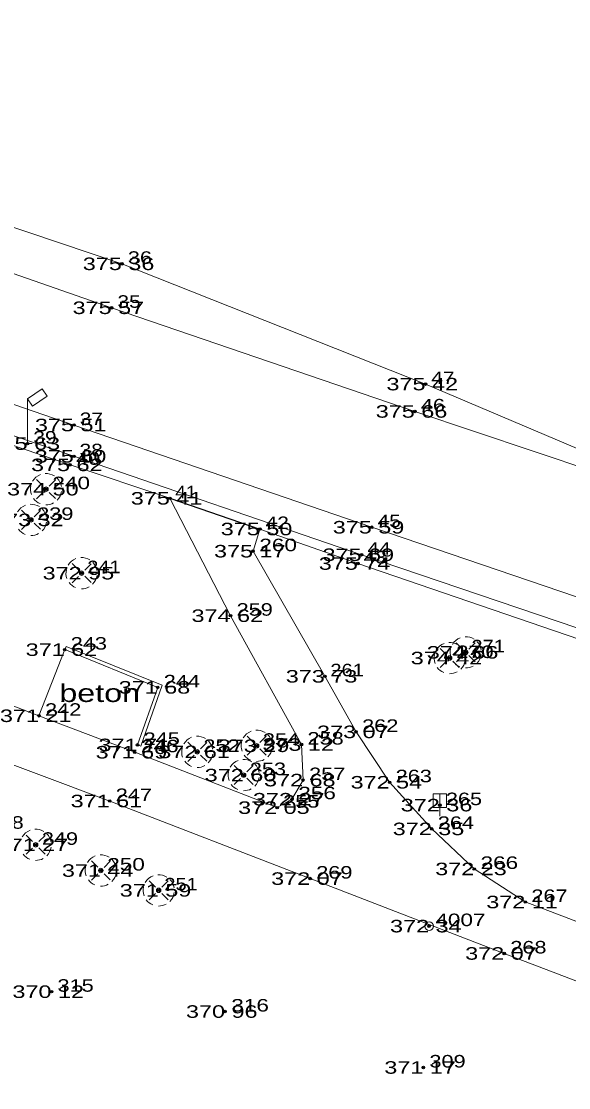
# Model space of a CAD drawing. Extents: x -789669 to -789458, y -977587 to -977420.
# Drawn here: x -789529.3 to -789498.6, y -977510.5 to -977450.8 of the extents above; entities that cross this region are included whole.
import ezdxf
from ezdxf.enums import TextEntityAlignment as Align

# ---------------------------------------------------------------- set-up
doc = ezdxf.new("R2010")
doc.units = 0
doc.header["$LTSCALE"] = 0.28
doc.header["$PDMODE"] = 32
doc.header["$PDSIZE"] = 0.14
for name, color, linetype, lineweight in [('1', 7, 'Continuous', 13), ('2', 7, 'Continuous', 13), ('25', 7, 'Continuous', 13), ('3', 7, 'Continuous', 13), ('33', 7, 'Continuous', 13), ('4', 7, 'Continuous', 13), ('50', 7, 'Continuous', 13)]:
    doc.layers.add(name, color=color, linetype=linetype, lineweight=lineweight)
for name, color, linetype in [('5', 7, 'Continuous'), ('57', 7, 'Continuous'), ('58', 7, 'Continuous'), ('59', 7, 'Continuous')]:
    doc.layers.add(name, color=color, linetype=linetype)

msp = doc.modelspace()

# ---------------------------------------------------------------- linework, layer by layer
at = {"layer": '1'}
msp.add_line((-789488.92, -977486.15), (-789509.64, -977479.12), dxfattribs=at)
for points in [[(-789652.33, -977422.61), (-789627.98, -977430.97), (-789609.02, -977437.54), (-789583.63, -977446.35), (-789563.97, -977453.25), (-789542.04, -977460.63), (-789524.21, -977466.84), (-789507.23, -977472.64), (-789487.17, -977479.36)], [(-789509.64, -977479.12), (-789526.32, -977473.4), (-789544.78, -977467.07), (-789566.2, -977459.68), (-789586.28, -977452.77), (-789604.78, -977446.41), (-789630.61, -977437.53), (-789654.9, -977429.37)], [(-789604.26, -977448.38), (-789586.79, -977454.41), (-789566.59, -977461.37), (-789545.35, -977468.71), (-789526.33, -977475.15), (-789510.21, -977480.66), (-789489.34, -977487.73), (-789463.94, -977496.44)], [(-789528.28, -977489.67), (-789537.88, -977485.96), (-789544.73, -977483.69), (-789553.55, -977480.4), (-789562.72, -977477.06), (-789579.25, -977471.12)], [(-789520.95, -977477.5), (-789517.55, -977484.07), (-789513.58, -977491.28), (-789513.49, -977493.27), (-789514.11, -977494.34), (-789514.94, -977494.81), (-789522.92, -977491.71)], [(-789467.42, -977508.6), (-789477.29, -977504.99), (-789481.22, -977505.18), (-789485.02, -977506.14), (-789492.68, -977503.27), (-789501.04, -977500.09), (-789503.9, -977498.24), (-789506.28, -977496), (-789508.64, -977493.39), (-789510.52, -977490.57), (-789512.27, -977487.46), (-789516.29, -977480.46), (-789515.91, -977479.22)], [(-789522.92, -977491.71), (-789528.28, -977489.67), (-789526.84, -977485.97)], [(-789542.34, -977487.22), (-789536.41, -977489.92), (-789524.32, -977494.44)], [(-789482.95, -977510.48), (-789493.26, -977506.39), (-789502.22, -977502.97), (-789513.09, -977498.78), (-789524.32, -977494.44)]]:
    msp.add_lwpolyline(points, dxfattribs=at)
at = {"layer": '2'}
msp.add_lwpolyline([(-789651.99, -977420.32), (-789627.42, -977429.7), (-789608.58, -977435.72), (-789582.71, -977444.73), (-789563.37, -977451.38), (-789541.29, -977458.45), (-789523.64, -977464.38), (-789506.63, -977471.11), (-789487.17, -977479.36)], dxfattribs=at)
at = {"layer": '25'}
msp.add_lwpolyline([(-789505.83, -977495.295), (-789505.83, -977494.045), (-789505.455, -977494.045), (-789505.455, -977494.795), (-789506.205, -977494.795), (-789506.205, -977494.045), (-789505.83, -977494.045)], dxfattribs=at)
at = {"layer": '3', "lineweight": 25}
msp.add_line((-789520.95, -977477.5), (-789515.91, -977479.22), dxfattribs=at)
at = {"layer": '3'}
for p, q in [((-789526.84, -977485.97), (-789526.765, -977485.785)), ((-789522.76, -977491.3), (-789522.571, -977491.366))]:
    msp.add_line(p, q, dxfattribs=at)
for points in [[(-789601.84, -977457.06), (-789598.55, -977450.95), (-789566.5, -977461.99), (-789545.47, -977469.2), (-789526.54, -977475.63), (-789520.95, -977477.5)], [(-789515.91, -977479.22), (-789510.42, -977481.15), (-789487.68, -977488.92), (-789464.26, -977497.04), (-789460.4, -977508.06)], [(-789526.84, -977485.97), (-789521.63, -977488.08), (-789522.76, -977491.3)], [(-789522.571, -977491.366), (-789521.378, -977487.966), (-789526.765, -977485.785)]]:
    msp.add_lwpolyline(points, dxfattribs=at)
at = {"layer": '33'}
for p, q in [((-789528.92, -977471.94), (-789528.92, -977474.44)), ((-789529.17, -977474.44), (-789528.67, -977474.44))]:
    msp.add_line(p, q, dxfattribs=at)
msp.add_lwpolyline([(-789528.92, -977471.94), (-789528.1, -977471.367), (-789527.814, -977471.777), (-789528.634, -977472.35)], close=True, dxfattribs=at)
at = {"layer": '4'}
for p, q in [((-789528.414, -977476.452), (-789528.057, -977476.808)), ((-789527.354, -977476.46), (-789527.707, -977476.813)), ((-789527.88, -977476.996), (-789527.88, -977476.984)), ((-789528.41, -977477.523), (-789528.058, -977477.172)), ((-789527.706, -977477.167), (-789527.354, -977477.517)), ((-789529.254, -977478.172), (-789528.897, -977478.528)), ((-789528.194, -977478.18), (-789528.547, -977478.533)), ((-789528.72, -977478.716), (-789528.72, -977478.704)), ((-789528.546, -977478.887), (-789528.194, -977479.237)), ((-789529.25, -977479.243), (-789528.898, -977478.892)), ((-789526.424, -977481.152), (-789526.067, -977481.508)), ((-789525.364, -977481.16), (-789525.717, -977481.513)), ((-789526.42, -977482.223), (-789526.068, -977481.872)), ((-789525.89, -977481.696), (-789525.89, -977481.684)), ((-789525.716, -977481.867), (-789525.364, -977482.217)), ((-789505.804, -977485.902), (-789505.447, -977486.258)), ((-789504.744, -977485.91), (-789505.097, -977486.263)), ((-789504.904, -977485.582), (-789504.547, -977485.938)), ((-789503.844, -977485.59), (-789504.197, -977485.943)), ((-789505.8, -977486.973), (-789505.448, -977486.622)), ((-789505.27, -977486.446), (-789505.27, -977486.434)), ((-789505.096, -977486.617), (-789504.744, -977486.967)), ((-789504.9, -977486.653), (-789504.548, -977486.302)), ((-789504.37, -977486.126), (-789504.37, -977486.114)), ((-789504.196, -977486.297), (-789503.844, -977486.647)), ((-789516.614, -977490.812), (-789516.257, -977491.168)), ((-789515.554, -977490.82), (-789515.907, -977491.173)), ((-789519.944, -977491.152), (-789519.587, -977491.508)), ((-789518.884, -977491.16), (-789519.237, -977491.513)), ((-789516.08, -977491.356), (-789516.08, -977491.344)), ((-789519.94, -977492.223), (-789519.588, -977491.872)), ((-789519.41, -977491.696), (-789519.41, -977491.684)), ((-789519.236, -977491.867), (-789518.884, -977492.217)), ((-789516.61, -977491.883), (-789516.258, -977491.532)), ((-789515.906, -977491.527), (-789515.554, -977491.877)), ((-789517.344, -977492.452), (-789516.987, -977492.808)), ((-789516.284, -977492.46), (-789516.637, -977492.813)), ((-789517.34, -977493.523), (-789516.988, -977493.172)), ((-789516.81, -977492.996), (-789516.81, -977492.984)), ((-789516.636, -977493.167), (-789516.284, -977493.517)), ((-789528.994, -977496.352), (-789528.637, -977496.708)), ((-789527.934, -977496.36), (-789528.287, -977496.713)), ((-789528.99, -977497.423), (-789528.638, -977497.072)), ((-789528.46, -977496.896), (-789528.46, -977496.884)), ((-789528.286, -977497.067), (-789527.934, -977497.417)), ((-789525.344, -977497.792), (-789524.987, -977498.148)), ((-789524.284, -977497.8), (-789524.637, -977498.153)), ((-789525.34, -977498.863), (-789524.988, -977498.512)), ((-789524.81, -977498.336), (-789524.81, -977498.324)), ((-789524.636, -977498.507), (-789524.284, -977498.857)), ((-789522.104, -977498.902), (-789521.747, -977499.258)), ((-789521.044, -977498.91), (-789521.397, -977499.263)), ((-789522.1, -977499.973), (-789521.748, -977499.622)), ((-789521.57, -977499.446), (-789521.57, -977499.434)), ((-789521.396, -977499.617), (-789521.044, -977499.967))]:
    msp.add_line(p, q, dxfattribs=at)
for centre in [(-789527.8839, -977476.9894), (-789528.7239, -977478.7094), (-789525.8939, -977481.6894), (-789504.3739, -977486.1194), (-789505.2739, -977486.4394), (-789516.0839, -977491.3494), (-789519.4139, -977491.6894), (-789516.8139, -977492.9894), (-789528.4639, -977496.8894), (-789524.8139, -977498.3294), (-789521.5739, -977499.4394)]:
    msp.add_circle(centre, 0.125, dxfattribs=at)
for centre, start, end in [((-789527.8839, -977476.9894), 111.04924, 149.34666), ((-789527.8839, -977476.9894), 57.94289, 92.85253), ((-789527.8839, -977476.9894), 9.68453, 44.47714), ((-789527.8839, -977476.9894), 166.76695, 200.11735), ((-789527.8839, -977476.9894), 217.06959, 247.69959), ((-789527.8839, -977476.9894), 315.09105, 351.67435), ((-789528.7239, -977478.7094), 111.04924, 149.34666), ((-789528.7239, -977478.7094), 57.94289, 92.85253), ((-789528.7239, -977478.7094), 9.68453, 44.47714), ((-789527.8839, -977476.9894), 269.18965, 298.56841), ((-789528.7239, -977478.7094), 315.09105, 351.67435), ((-789528.7239, -977478.7094), 217.06959, 247.69959), ((-789528.7239, -977478.7094), 269.18965, 298.56841), ((-789525.8939, -977481.6894), 111.04924, 149.34666), ((-789525.8939, -977481.6894), 57.94289, 92.85253), ((-789525.8939, -977481.6894), 9.68453, 44.47714), ((-789525.8939, -977481.6894), 166.76695, 200.11735), ((-789525.8939, -977481.6894), 315.09105, 351.67435), ((-789525.8939, -977481.6894), 217.06959, 247.69959), ((-789525.8939, -977481.6894), 269.18965, 298.56841), ((-789504.3739, -977486.1194), 111.04924, 149.34666), ((-789504.3739, -977486.1194), 57.94289, 92.85253), ((-789505.2739, -977486.4394), 111.04924, 149.34666), ((-789505.2739, -977486.4394), 57.94289, 92.85253), ((-789504.3739, -977486.1194), 166.76695, 200.11735), ((-789505.2739, -977486.4394), 9.68453, 44.47714), ((-789504.3739, -977486.1194), 9.68453, 44.47714), ((-789505.2739, -977486.4394), 166.76695, 200.11735), ((-789505.2739, -977486.4394), 315.09105, 351.67435), ((-789504.3739, -977486.1194), 315.09105, 351.67435), ((-789505.2739, -977486.4394), 217.06959, 247.69959), ((-789505.2739, -977486.4394), 269.18965, 298.56841), ((-789504.3739, -977486.1194), 217.06959, 247.69959), ((-789504.3739, -977486.1194), 269.18965, 298.56841), ((-789519.4139, -977491.6894), 57.94289, 92.85253), ((-789516.0839, -977491.3494), 111.04924, 149.34666), ((-789516.0839, -977491.3494), 57.94289, 92.85253), ((-789516.0839, -977491.3494), 9.68453, 44.47714), ((-789519.4139, -977491.6894), 111.04924, 149.34666), ((-789519.4139, -977491.6894), 9.68453, 44.47714), ((-789516.0839, -977491.3494), 166.76695, 200.11735), ((-789519.4139, -977491.6894), 166.76695, 200.11735), ((-789519.4139, -977491.6894), 315.09105, 351.67435), ((-789516.0839, -977491.3494), 217.06959, 247.69959), ((-789516.0839, -977491.3494), 315.09105, 351.67435), ((-789519.4139, -977491.6894), 217.06959, 247.69959), ((-789519.4139, -977491.6894), 269.18965, 298.56841), ((-789516.8139, -977492.9894), 111.04924, 149.34666), ((-789516.8139, -977492.9894), 57.94289, 92.85253), ((-789516.8139, -977492.9894), 9.68453, 44.47714), ((-789516.0839, -977491.3494), 269.18965, 298.56841), ((-789516.8139, -977492.9894), 166.76695, 200.11735), ((-789516.8139, -977492.9894), 315.09105, 351.67435), ((-789516.8139, -977492.9894), 217.06959, 247.69959), ((-789516.8139, -977492.9894), 269.18965, 298.56841), ((-789528.4639, -977496.8894), 111.04924, 149.34666), ((-789528.4639, -977496.8894), 57.94289, 92.85253), ((-789528.4639, -977496.8894), 9.68453, 44.47714), ((-789528.4639, -977496.8894), 315.09105, 351.67435), ((-789528.4639, -977496.8894), 217.06959, 247.69959), ((-789528.4639, -977496.8894), 269.18965, 298.56841), ((-789524.8139, -977498.3294), 111.04924, 149.34666), ((-789524.8139, -977498.3294), 57.94289, 92.85253), ((-789524.8139, -977498.3294), 9.68453, 44.47714), ((-789524.8139, -977498.3294), 166.76695, 200.11735), ((-789524.8139, -977498.3294), 315.09105, 351.67435), ((-789521.5739, -977499.4394), 57.94289, 92.85253), ((-789524.8139, -977498.3294), 217.06959, 247.69959), ((-789524.8139, -977498.3294), 269.18965, 298.56841), ((-789521.5739, -977499.4394), 111.04924, 149.34666), ((-789521.5739, -977499.4394), 9.68453, 44.47714), ((-789521.5739, -977499.4394), 166.76695, 200.11735), ((-789521.5739, -977499.4394), 315.09105, 351.67435), ((-789521.5739, -977499.4394), 217.06959, 247.69959), ((-789521.5739, -977499.4394), 269.18965, 298.56841)]:
    msp.add_arc(centre, 0.875, start, end, dxfattribs=at)
at = {"layer": '50'}
msp.add_line((-789506.438, -977501.44), (-789506.422, -977501.44), dxfattribs=at)
msp.add_circle((-789506.4298, -977501.4405), 0.24, dxfattribs=at)
at = {"layer": '57'}
for p in [(-789523.64, -977464.38), (-789524.21, -977466.84), (-789506.63, -977471.11), (-789507.23, -977472.64), (-789526.32, -977473.4), (-789528.92, -977474.44), (-789526.33, -977475.15), (-789526.54, -977475.63), (-789527.88, -977476.99), (-789520.95, -977477.5), (-789528.72, -977478.71), (-789515.91, -977479.22), (-789509.64, -977479.12), (-789516.29, -977480.46), (-789510.21, -977480.66), (-789510.42, -977481.15), (-789525.89, -977481.69), (-789517.55, -977484.07), (-789526.84, -977485.97), (-789505.27, -977486.44), (-789504.37, -977486.12), (-789512.27, -977487.46), (-789521.63, -977488.08), (-789528.28, -977489.67), (-789510.52, -977490.57), (-789522.76, -977491.3), (-789516.08, -977491.35), (-789513.58, -977491.28), (-789522.92, -977491.71), (-789519.41, -977491.69), (-789516.81, -977492.99), (-789513.49, -977493.27), (-789508.64, -977493.39), (-789524.32, -977494.44), (-789514.11, -977494.34), (-789514.94, -977494.81), (-789505.83, -977494.67), (-789506.28, -977496), (-789528.46, -977496.89), (-789524.81, -977498.33), (-789503.9, -977498.24), (-789513.09, -977498.78), (-789521.57, -977499.44), (-789501.04, -977500.09), (-789506.43, -977501.44), (-789502.22, -977502.97), (-789527.58, -977505.11), (-789517.86, -977506.22), (-789506.75, -977509.35)]:
    msp.add_point(p, dxfattribs=at)

# ---------------------------------------------------------------- texts
at = {"layer": '5', "width": 1.35}
msp.add_text('beton', height=1, dxfattribs=at).set_placement((-789527.138, -977488.899))
at = {"layer": '50', "width": 1.35}
msp.add_text(' 4007', height=0.7, dxfattribs=at).set_placement((-789506.43, -977501.44))
at = {"layer": '58'}
for s, width, p in [(' 36', 1.3, (-789523.64, -977464.38)), (' 35', 1.25, (-789524.21, -977466.84)), (' 47', 1.25, (-789506.63, -977471.11)), (' 46', 1.3, (-789507.23, -977472.64)), (' 37', 1.25, (-789526.32, -977473.4)), (' 39', 1.25, (-789528.92, -977474.44)), (' 38', 1.25, (-789526.33, -977475.15)), (' 40', 1.3, (-789526.54, -977475.63)), (' 240', 1.35, (-789527.88, -977476.99)), (' 41', 1.15, (-789520.95, -977477.5)), (' 239', 1.3, (-789528.72, -977478.71)), (' 42', 1.25, (-789515.91, -977479.22)), (' 45', 1.25, (-789509.64, -977479.12)), (' 260', 1.35, (-789516.29, -977480.46)), (' 44', 1.25, (-789510.21, -977480.66)), (' 43', 1.25, (-789510.42, -977481.15)), (' 241', 1.2, (-789525.89, -977481.69)), (' 259', 1.3, (-789517.55, -977484.07)), (' 243', 1.3, (-789526.84, -977485.97)), (' 271', 1.2, (-789504.37, -977486.12)), (' 270', 1.35, (-789505.27, -977486.44)), (' 261', 1.2, (-789512.27, -977487.46)), (' 244', 1.3, (-789521.63, -977488.08)), (' 242', 1.3, (-789528.28, -977489.67)), (' 262', 1.3, (-789510.52, -977490.57)), (' 245', 1.3, (-789522.76, -977491.3)), (' 254', 1.3, (-789516.08, -977491.35)), (' 258', 1.3, (-789513.58, -977491.28)), (' 246', 1.35, (-789522.92, -977491.71)), (' 252', 1.3, (-789519.41, -977491.69)), (' 253', 1.3, (-789516.81, -977492.99)), (' 257', 1.3, (-789513.49, -977493.27)), (' 263', 1.3, (-789508.64, -977493.39)), (' 247', 1.3, (-789524.32, -977494.44)), (' 256', 1.35, (-789514.11, -977494.34)), (' 255', 1.3, (-789514.94, -977494.81)), (' 265', 1.3, (-789505.83, -977494.67)), (' 248', 1.3, (-789531.5, -977495.99)), (' 264', 1.3, (-789506.28, -977496)), (' 249', 1.3, (-789528.46, -977496.89)), (' 250', 1.35, (-789524.81, -977498.33)), (' 266', 1.35, (-789503.9, -977498.24)), (' 269', 1.3, (-789513.09, -977498.78)), (' 251', 1.2, (-789521.57, -977499.44)), (' 267', 1.3, (-789501.04, -977500.09)), (' 4007', 1.35, (-789506.43, -977501.44)), (' 268', 1.3, (-789502.22, -977502.97)), (' 315', 1.3, (-789527.58, -977505.11)), (' 316', 1.35, (-789517.86, -977506.22)), (' 309', 1.3, (-789506.75, -977509.35))]:
    msp.add_text(s, height=0.7, dxfattribs=dict(at, width=width)).set_placement(p)
at = {"layer": '59', "width": 1.4}
for s, p in [('375 36 ', (-789523.64, -977464.73)), ('375 57 ', (-789524.21, -977467.19)), ('375 42 ', (-789506.63, -977471.46)), ('375 66 ', (-789507.23, -977472.99)), ('375 51 ', (-789526.32, -977473.75)), ('375 63 ', (-789528.92, -977474.79)), ('375 62 ', (-789526.54, -977475.98)), ('375 60 ', (-789526.33, -977475.5)), ('374 50 ', (-789527.88, -977477.34)), ('375 41 ', (-789520.95, -977477.85)), ('373 32 ', (-789528.72, -977479.06)), ('375 50 ', (-789515.91, -977479.57)), ('375 59 ', (-789509.64, -977479.47)), ('375 17 ', (-789516.29, -977480.81)), ('375 69 ', (-789510.21, -977481.01)), ('375 74 ', (-789510.42, -977481.5)), ('372 95 ', (-789525.89, -977482.04)), ('374 62 ', (-789517.55, -977484.42)), ('371 62 ', (-789526.84, -977486.32)), ('374 66 ', (-789504.37, -977486.47)), ('374 42 ', (-789505.27, -977486.79)), ('373 73 ', (-789512.27, -977487.81)), ('371 68 ', (-789521.63, -977488.43)), ('371 21 ', (-789528.28, -977490.02)), ('373 07 ', (-789510.52, -977490.92)), ('371 69 ', (-789522.92, -977492.06)), ('371 71 ', (-789522.76, -977491.65)), ('372 61 ', (-789519.41, -977492.04)), ('373 29 ', (-789516.08, -977491.7)), ('373 12 ', (-789513.58, -977491.63)), ('372 60 ', (-789516.81, -977493.34)), ('372 68 ', (-789513.49, -977493.62)), ('372 54 ', (-789508.64, -977493.74)), ('371 61 ', (-789524.32, -977494.79)), ('372 27 ', (-789514.11, -977494.69)), ('372 36 ', (-789505.83, -977495.02)), ('372 05 ', (-789514.94, -977495.16)), ('372 35 ', (-789506.28, -977496.35)), ('371 27 ', (-789528.46, -977497.24)), ('371 44 ', (-789524.81, -977498.68)), ('372 23 ', (-789503.9, -977498.59)), ('372 07 ', (-789513.09, -977499.13)), ('371 59 ', (-789521.57, -977499.79)), ('372 11 ', (-789501.04, -977500.44)), ('372 34 ', (-789506.43, -977501.79)), ('372 07 ', (-789502.22, -977503.32)), ('370 12 ', (-789527.58, -977505.46)), ('370 96 ', (-789517.86, -977506.57)), ('371 17 ', (-789506.75, -977509.7))]:
    msp.add_text(s, height=0.7, dxfattribs=at).set_placement(p, align=Align.CENTER)

doc.saveas('drawing.dxf')
